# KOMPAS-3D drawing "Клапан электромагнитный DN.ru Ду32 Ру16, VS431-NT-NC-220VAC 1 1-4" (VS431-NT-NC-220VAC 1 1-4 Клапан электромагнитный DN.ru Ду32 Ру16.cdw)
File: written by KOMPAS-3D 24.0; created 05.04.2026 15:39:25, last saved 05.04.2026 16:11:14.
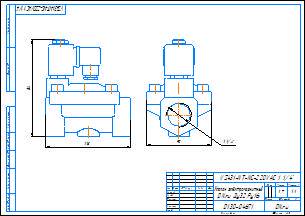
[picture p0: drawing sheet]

Document properties: c3d_UniqueCompID: ef56311e-7521-43dc-8291-0e6108b3d81d; Автор: artio; Класс точности: c; Знак неуказанной шероховатости: Шероховатость не задана; Рассекать на разрезах: Да; c3d_UniqueCompID: ef56311e-7521-43dc-8291-0e6108b3d81d; Автор: artio; Класс точности: c; Знак неуказанной шероховатости: Шероховатость не задана; Рассекать на разрезах: Да; c3d_UniqueCompID: ef56311e-7521-43dc-8291-0e6108b3d81d; Автор: artio; Класс точности: c; Знак неуказанной шероховатости: Шероховатость не задана; Рассекать на разрезах: Да; Автор: artio; Форматы листов документа: A3; Полное имя файла: VS431-NT-NC-220VAC 1 1-4 Клапан электромагнитный DN.ru Ду32 Ру16.m3d; Масса: 1.701; Наименование: Клапан электромагнитный DN.ru Ду32 Ру16; Количество листов документа: 1; Примечание: D130-04671

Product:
- Body: Тело 1  | qty 1
    Масса: 3.709873
- Part/product: Клапан электромагнитный DN.ru Ду32 Ру16  | designation VS431-NT-NC-220VAC 1 1-4
    Масса: 1.701
    Раздел спецификации: Прочие изделия
    Примечание: D130-04671
    additional columns: ef56311e-7521-43dc-8291-0e6108b3d81d; artio; c; Шероховатость не задана; Да

Views: Вид 1, Спереди
Referenced files in C:\Users\artio\OneDrive\Рабочий стол\Клапан электромагнитный DN.ru\VS431\VS431-ET-NC\: VS431-ET-NC-220VAC 3-4 Клапан электромагнитный DN.ru Ду20 Ру16.m3d, VS431-ET-NC-220VAC 3-4 Клапан электромагнитный DN.ru Ду20 Ру16.cdw
Referenced files in C:\Users\artio\OneDrive\Рабочий стол\Клапан электромагнитный DN.ru\VS431\VS431-NT-NC\: VS431-NT-NC-220VAC 1 1-4 Клапан электромагнитный DN.ru Ду32 Ру16.m3d
Referenced files in C:\Users\artio\OneDrive\Рабочий стол\Клапан электромагнитный DN.ru\VS431\VS431-NT-NC\VS431-NT-NC-220VAC\Ду32\: VS431-NT-NC-220VAC 1 1-4 Клапан электромагнитный DN.ru Ду32 Ру16.m3d
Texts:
  VS431-NT-NC-220VAC 1 1-4
  Клапан электромагнитный
  DN.ru Ду32 Ру16
  VS431-NT-NC-220VAC 1 1/4"
  VS431-NT-NC-220VAC 1 1/4"-
  Клапан электромагнитный DN.ru Ду32 Ру16
  VS431-NT-NC-220VAC 1 1-4 Клапан электромагнитный DN.ru Ду32 Ру16
Dimensions and other numbers on the sheet: 0; 3; 2; 4; 90; 1 1/4"; 1:1; 1; 1,7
